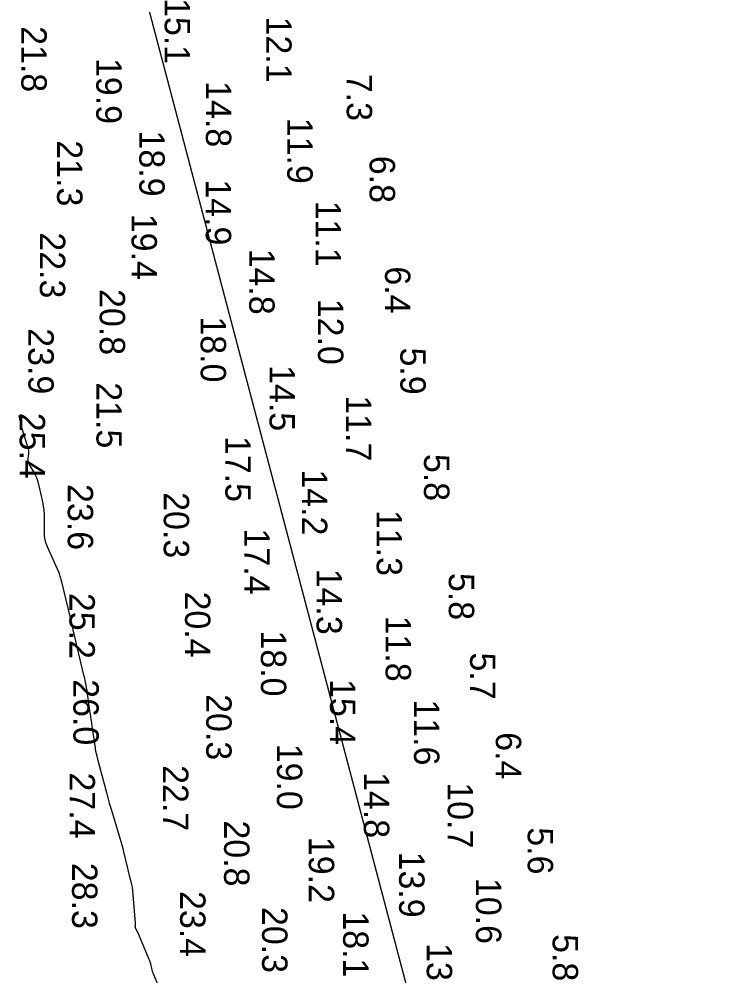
# Model space of a CAD drawing. Extents: x 1178573 to 1187098, y 693282 to 751751.
# Drawn here: x 1182473 to 1182821.7, y 743891.7 to 744362.9 of the extents above; entities that cross this region are included whole.
import ezdxf

# ---------------------------------------------------------------- set-up
doc = ezdxf.new("R2010")
doc.units = 0
for name, color, linetype in [('G-ANNO-PATT', 7, 'Continuous'), ('V-HYDS-MAJR', 7, 'Continuous'), ('V-HYDS-SOUN', 7, 'Continuous'), ('V-HYDS-SOUN-EXSS', 7, 'Continuous')]:
    doc.layers.add(name, color=color, linetype=linetype)

msp = doc.modelspace()

# ---------------------------------------------------------------- linework, layer by layer
at = {"layer": 'G-ANNO-PATT'}
for p, q in [((1182821.74, 743288.49), (1182496.73, 744520.52)), ((1182472.88, 744167.62), (1182473.19, 744165.86)), ((1182473.19, 744165.86), (1182473.57, 744164.12)), ((1182473.57, 744164.12), (1182474, 744162.39)), ((1182474, 744162.39), (1182474.5, 744160.68)), ((1182474.5, 744160.68), (1182477.28, 744151.77)), ((1182477.28, 744151.77), (1182477.45, 744151.1)), ((1182477.45, 744151.1), (1182477.55, 744150.43)), ((1182477.22, 744146.31), (1182477.19, 744145.63)), ((1182477.53, 744149.07), (1182477.22, 744146.31)), ((1182477.57, 744149.75), (1182477.53, 744149.07)), ((1182477.55, 744150.43), (1182477.57, 744149.75)), ((1182477.19, 744145.63), (1182477.28, 744144.98)), ((1182477.28, 744144.98), (1182477.47, 744144.35)), ((1182477.47, 744144.35), (1182477.77, 744143.74)), ((1182477.77, 744143.74), (1182480.5, 744139.12)), ((1182480.5, 744139.12), (1182481.03, 744138.14)), ((1182481.03, 744138.14), (1182481.49, 744137.12)), ((1182481.49, 744137.12), (1182481.86, 744136.08)), ((1182481.86, 744136.08), (1182482.16, 744135)), ((1182482.16, 744135), (1182483.78, 744128.08)), ((1182483.78, 744128.08), (1182483.96, 744127.33)), ((1182483.96, 744127.33), (1182484.12, 744126.58)), ((1182484.12, 744126.58), (1182484.28, 744125.83)), ((1182484.28, 744125.83), (1182484.42, 744125.08)), ((1182484.42, 744125.08), (1182485, 744122.06)), ((1182485, 744122.06), (1182485.12, 744121.3)), ((1182485.12, 744121.3), (1182485.21, 744120.54)), ((1182485.21, 744120.54), (1182485.26, 744119.78)), ((1182485.26, 744119.78), (1182485.28, 744119.01)), ((1182485.28, 744119.01), (1182485.26, 744109.92)), ((1182485.26, 744109.92), (1182485.35, 744108.17)), ((1182485.35, 744108.17), (1182485.62, 744106.45)), ((1182485.62, 744106.45), (1182486.08, 744104.78)), ((1182486.08, 744104.78), (1182486.72, 744103.15)), ((1182486.72, 744103.15), (1182492.36, 744090.69)), ((1182492.36, 744090.69), (1182492.47, 744090.44)), ((1182492.47, 744090.44), (1182492.57, 744090.18)), ((1182492.57, 744090.18), (1182492.66, 744089.92)), ((1182492.66, 744089.92), (1182492.75, 744089.65)), ((1182492.75, 744089.65), (1182493.11, 744088.38)), ((1182493.11, 744088.38), (1182493.16, 744088.22)), ((1182493.16, 744088.22), (1182493.21, 744088.05)), ((1182493.21, 744088.05), (1182493.26, 744087.88)), ((1182493.26, 744087.88), (1182493.31, 744087.71)), ((1182493.31, 744087.71), (1182493.51, 744087.03)), ((1182493.51, 744087.03), (1182493.55, 744086.86)), ((1182493.55, 744086.86), (1182493.6, 744086.7)), ((1182493.6, 744086.7), (1182493.65, 744086.52)), ((1182493.65, 744086.52), (1182493.69, 744086.35)), ((1182493.69, 744086.35), (1182499.08, 744063.97)), ((1182499.08, 744063.97), (1182499.13, 744063.76)), ((1182499.13, 744063.76), (1182499.17, 744063.56)), ((1182499.17, 744063.56), (1182499.22, 744063.35)), ((1182499.22, 744063.35), (1182499.26, 744063.14)), ((1182499.26, 744063.14), (1182499.43, 744062.3)), ((1182499.43, 744062.3), (1182499.48, 744062.09)), ((1182499.48, 744062.09), (1182499.52, 744061.88)), ((1182499.52, 744061.88), (1182499.57, 744061.67)), ((1182499.57, 744061.67), (1182499.62, 744061.46)), ((1182499.62, 744061.46), (1182504.77, 744039.76)), ((1182504.77, 744039.76), (1182504.96, 744038.91)), ((1182504.96, 744038.91), (1182505.15, 744038.05)), ((1182505.15, 744038.05), (1182505.32, 744037.19)), ((1182505.32, 744037.19), (1182505.49, 744036.33)), ((1182505.49, 744036.33), (1182506.12, 744032.89)), ((1182506.12, 744032.89), (1182506.27, 744032.03)), ((1182506.27, 744032.03), (1182506.42, 744031.17)), ((1182506.42, 744031.17), (1182506.56, 744030.3)), ((1182506.56, 744030.3), (1182506.69, 744029.44)), ((1182506.69, 744029.44), (1182507.87, 744021.21)), ((1182507.87, 744021.21), (1182508.11, 744019.55)), ((1182508.11, 744019.55), (1182508.35, 744017.89)), ((1182508.35, 744017.89), (1182508.59, 744016.23)), ((1182508.59, 744016.23), (1182508.83, 744014.57)), ((1182508.83, 744014.57), (1182510.38, 744003.95)), ((1182510.38, 744003.95), (1182510.45, 744003.54)), ((1182510.45, 744003.54), (1182510.52, 744003.13)), ((1182510.52, 744003.13), (1182510.6, 744002.72)), ((1182510.6, 744002.72), (1182510.69, 744002.32)), ((1182510.69, 744002.32), (1182511.06, 744000.69)), ((1182511.06, 744000.69), (1182511.15, 744000.29)), ((1182511.15, 744000.29), (1182511.25, 743999.88)), ((1182511.25, 743999.88), (1182511.35, 743999.48)), ((1182511.35, 743999.48), (1182511.45, 743999.08)), ((1182511.45, 743999.08), (1182515.98, 743981.96)), ((1182515.98, 743981.96), (1182516.68, 743979.36)), ((1182516.68, 743979.36), (1182517.41, 743976.76)), ((1182517.41, 743976.76), (1182518.15, 743974.17)), ((1182518.15, 743974.17), (1182518.93, 743971.59)), ((1182518.93, 743971.59), (1182522.6, 743959.49)), ((1182522.6, 743959.49), (1182523.1, 743957.8)), ((1182523.1, 743957.8), (1182523.57, 743956.11)), ((1182523.57, 743956.11), (1182524.01, 743954.41)), ((1182524.01, 743954.41), (1182524.42, 743952.7)), ((1182524.42, 743952.7), (1182526.48, 743943.87)), ((1182526.48, 743943.87), (1182526.66, 743943.15)), ((1182526.66, 743943.15), (1182526.84, 743942.43)), ((1182526.84, 743942.43), (1182527.03, 743941.72)), ((1182527.03, 743941.72), (1182527.23, 743941.01)), ((1182527.23, 743941.01), (1182528.05, 743938.17)), ((1182528.05, 743938.17), (1182528.24, 743937.45)), ((1182528.24, 743937.45), (1182528.39, 743936.73)), ((1182528.39, 743936.73), (1182528.51, 743936.01)), ((1182528.51, 743936.01), (1182528.6, 743935.27)), ((1182528.6, 743935.27), (1182530.19, 743917.73)), ((1182530.08, 743916.19), (1182530.07, 743916)), ((1182530.07, 743916), (1182530.09, 743915.81)), ((1182530.18, 743916.96), (1182530.08, 743916.19)), ((1182530.09, 743915.81), (1182530.13, 743915.63)), ((1182530.13, 743915.63), (1182530.2, 743915.45)), ((1182530.2, 743917.15), (1182530.18, 743916.96)), ((1182530.19, 743917.73), (1182530.2, 743917.54)), ((1182530.2, 743917.54), (1182530.21, 743917.34)), ((1182530.21, 743917.34), (1182530.2, 743917.15)), ((1182530.2, 743915.45), (1182531.18, 743913.39)), ((1182531.18, 743913.39), (1182531.37, 743912.98)), ((1182531.37, 743912.98), (1182531.56, 743912.58)), ((1182531.56, 743912.58), (1182531.74, 743912.17)), ((1182531.74, 743912.17), (1182531.91, 743911.76)), ((1182531.91, 743911.76), (1182536.94, 743899.84)), ((1182536.94, 743899.84), (1182537.17, 743899.28)), ((1182537.17, 743899.28), (1182537.36, 743898.71)), ((1182537.36, 743898.71), (1182537.54, 743898.14)), ((1182537.54, 743898.14), (1182537.69, 743897.55)), ((1182537.69, 743897.55), (1182538.24, 743895.2)), ((1182538.24, 743895.2), (1182538.39, 743894.62)), ((1182538.39, 743894.62), (1182538.57, 743894.04)), ((1182538.57, 743894.04), (1182538.76, 743893.47)), ((1182538.76, 743893.47), (1182538.98, 743892.9)), ((1182538.98, 743892.9), (1182542.3, 743884.74))]:
    msp.add_line(p, q, dxfattribs=at)
at = {"layer": 'V-HYDS-MAJR'}
msp.add_lwpolyline([(1182472.88, 744167.62), (1182473.19, 744165.86), (1182473.57, 744164.12), (1182474, 744162.39), (1182474.5, 744160.68), (1182477.28, 744151.77), (1182477.45, 744151.1), (1182477.55, 744150.43), (1182477.57, 744149.75), (1182477.53, 744149.07), (1182477.22, 744146.31), (1182477.19, 744145.63), (1182477.28, 744144.98), (1182477.47, 744144.35), (1182477.77, 744143.74), (1182480.5, 744139.12), (1182481.03, 744138.14), (1182481.49, 744137.12), (1182481.86, 744136.08), (1182482.16, 744135), (1182483.78, 744128.08), (1182483.96, 744127.33), (1182484.12, 744126.58), (1182484.28, 744125.83), (1182484.42, 744125.08), (1182485, 744122.06), (1182485.12, 744121.3), (1182485.21, 744120.54), (1182485.26, 744119.78), (1182485.28, 744119.01), (1182485.26, 744109.92), (1182485.35, 744108.17), (1182485.62, 744106.45), (1182486.08, 744104.78), (1182486.72, 744103.15), (1182492.36, 744090.69), (1182492.47, 744090.44), (1182492.57, 744090.18), (1182492.66, 744089.92), (1182492.75, 744089.65), (1182493.11, 744088.38), (1182493.16, 744088.22), (1182493.21, 744088.05), (1182493.26, 744087.88), (1182493.31, 744087.71), (1182493.51, 744087.03), (1182493.55, 744086.86), (1182493.6, 744086.7), (1182493.65, 744086.52), (1182493.69, 744086.35), (1182499.08, 744063.97), (1182499.13, 744063.76), (1182499.17, 744063.56), (1182499.22, 744063.35), (1182499.26, 744063.14), (1182499.43, 744062.3), (1182499.48, 744062.09), (1182499.52, 744061.88), (1182499.57, 744061.67), (1182499.62, 744061.46), (1182504.77, 744039.76), (1182504.96, 744038.91), (1182505.15, 744038.05), (1182505.32, 744037.19), (1182505.49, 744036.33), (1182506.12, 744032.89), (1182506.27, 744032.03), (1182506.42, 744031.17), (1182506.56, 744030.3), (1182506.69, 744029.44), (1182507.87, 744021.21), (1182508.11, 744019.55), (1182508.35, 744017.89), (1182508.59, 744016.23), (1182508.83, 744014.57), (1182510.38, 744003.95), (1182510.45, 744003.54), (1182510.52, 744003.13), (1182510.6, 744002.72), (1182510.69, 744002.32), (1182511.06, 744000.69), (1182511.15, 744000.29), (1182511.25, 743999.88), (1182511.35, 743999.48), (1182511.45, 743999.08), (1182515.98, 743981.96), (1182516.68, 743979.36), (1182517.41, 743976.76), (1182518.15, 743974.17), (1182518.93, 743971.59), (1182522.6, 743959.49), (1182523.1, 743957.8), (1182523.57, 743956.11), (1182524.01, 743954.41), (1182524.42, 743952.7), (1182526.48, 743943.87), (1182526.66, 743943.15), (1182526.84, 743942.43), (1182527.03, 743941.72), (1182527.23, 743941.01), (1182528.05, 743938.17), (1182528.24, 743937.45), (1182528.39, 743936.73), (1182528.51, 743936.01), (1182528.6, 743935.27), (1182530.19, 743917.73), (1182530.2, 743917.54), (1182530.21, 743917.34), (1182530.2, 743917.15), (1182530.18, 743916.96), (1182530.08, 743916.19), (1182530.07, 743916), (1182530.09, 743915.81), (1182530.13, 743915.63), (1182530.2, 743915.45), (1182531.18, 743913.39), (1182531.37, 743912.98), (1182531.56, 743912.58), (1182531.74, 743912.17), (1182531.91, 743911.76), (1182536.94, 743899.84), (1182537.17, 743899.28), (1182537.36, 743898.71), (1182537.54, 743898.14), (1182537.69, 743897.55), (1182538.24, 743895.2), (1182538.39, 743894.62), (1182538.57, 743894.04), (1182538.76, 743893.47), (1182538.98, 743892.9), (1182542.3, 743884.74)], dxfattribs=at)

# ---------------------------------------------------------------- texts
at = {"layer": 'V-HYDS-SOUN'}
for s, p in [('15.1 ', (1182544.69, 744373.25)), ('21.8 ', (1182474.08, 744359.41)), ('12.1 ', (1182594.72, 744364.13)), ('19.9 ', (1182510.99, 744343.73)), ('7.3', (1182634.42, 744335.93)), ('14.8 ', (1182565, 744332.32)), ('11.9 ', (1182605.12, 744314.3)), ('18.9 ', (1182532.22, 744308)), ('21.3 ', (1182491.69, 744303.18)), ('6.8', (1182645.7, 744295.55)), ('14.9 ', (1182564.96, 744283.96)), ('11.1 ', (1182619.03, 744273.48)), ('19.4 ', (1182528.37, 744267)), ('22.3 ', (1182483.19, 744257.87)), ('14.8 ', (1182586.35, 744249.83)), ('6.4', (1182653.28, 744241.09)), ('20.8 ', (1182512.67, 744229.92)), ('12.0 ', (1182620.27, 744225.14)), ('18.0 ', (1182562.43, 744216.45)), ('23.9 ', (1182477.53, 744210.63)), ('5.9', (1182660.83, 744201.13)), ('14.5 ', (1182596.36, 744192.47)), ('21.5 ', (1182511.06, 744184)), ('11.7 ', (1182634.08, 744177.62)), ('25.4 ', (1182473.25, 744169)), ('17.5 ', (1182574.61, 744157.59)), ('5.8', (1182672.51, 744148.74)), ('14.2 ', (1182612.32, 744141.14)), ('23.6 ', (1182496.94, 744133.89)), ('20.3 ', (1182544.25, 744129.89)), ('11.3 ', (1182649.17, 744121.13)), ('17.4 ', (1182583.95, 744111.99)), ('14.3 ', (1182619.55, 744092.22)), ('5.8', (1182684.71, 744090.11)), ('25.2 ', (1182497.78, 744080.28)), ('20.4 ', (1182554.72, 744080.95)), ('11.8 ', (1182653.58, 744069.09)), ('18.0 ', (1182592.12, 744061.79)), ('5.7', (1182695.21, 744050.93)), ('26.0 ', (1182499.7, 744037.77)), ('15.4 ', (1182626.21, 744037.87)), ('20.3 ', (1182565.18, 744030.41)), ('11.6 ', (1182667.58, 744027.82)), ('19.0 ', (1182600.02, 744005.98)), ('27.4 ', (1182497.83, 743991.84)), ('22.7 ', (1182543.86, 743995.44)), ('10.7 ', (1182684.18, 743987.01)), ('5.6', (1182723.59, 743964.84)), ('19.2 ', (1182615.73, 743960.1)), ('13.9 ', (1182660.24, 743952.85)), ('10.6 ', (1182698.09, 743939.9)), ('23.4 ', (1182552.32, 743933.44)), ('20.3 ', (1182592.71, 743925.59)), ('18.1 ', (1182632.65, 743923.42)), ('5.8', (1182735.89, 743912.22)), ('13.8 ', (1182673.85, 743907.81))]:
    msp.add_text(s, height=12.5, rotation=270, dxfattribs=at).set_placement(p)
at = {"layer": 'V-HYDS-SOUN-EXSS'}
for s, p in [('6.4', (1182707.88, 744011.66)), ('14.8 ', (1182642.88, 743992.03)), ('20.8 ', (1182573.98, 743968.21)), ('28.3 ', (1182499.07, 743947.34))]:
    msp.add_text(s, height=12.5, rotation=270, dxfattribs=at).set_placement(p)

doc.saveas('drawing.dxf')
